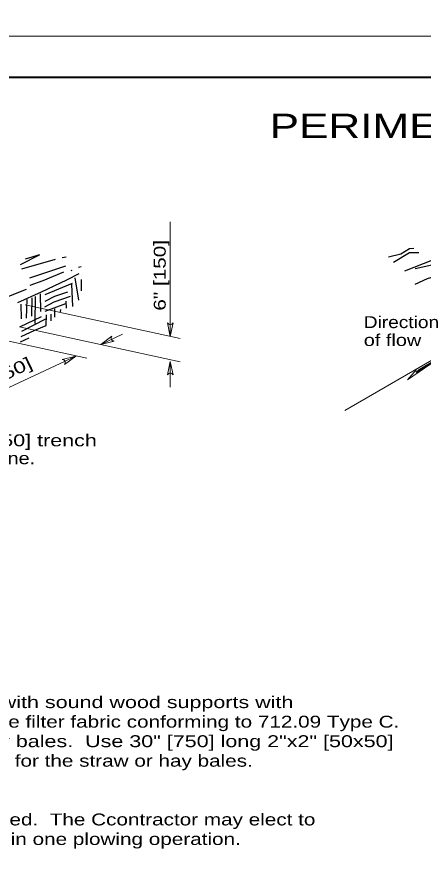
# Model space of a CAD drawing. Extents: x 1083.1 to 1117.1, y 672.5 to 716.5.
# Drawn here: x 1092.18 to 1097.5, y 683.63 to 694.76 of the extents above; entities that cross this region are included whole.
import ezdxf
from ezdxf.enums import TextEntityAlignment as Align

# ---------------------------------------------------------------- set-up
doc = ezdxf.new("R2010")
doc.units = 0
doc.header["$LTSCALE"] = 0.062
doc.linetypes.add('LONG_DASHED', pattern=[7.5, 6, -1.5])
doc.layers.add('1', color=7, linetype='Continuous', lineweight=13)

msp = doc.modelspace()

# ---------------------------------------------------------------- linework, layer by layer
at = {"layer": '1', "lineweight": 25}
for p, q in [((1085.14617, 693.96842), (1116.64617, 693.96842)), ((1092.24067, 691.4565), (1092.684, 691.58508)), ((1092.77267, 691.60783), (1092.82592, 691.61542)), ((1097.26167, 691.43017), (1097.63042, 691.5765)), ((1092.34708, 691.33925), (1092.81883, 691.49817)), ((1092.88975, 691.43758), (1092.90392, 691.44142)), ((1092.9855, 691.47925), (1093.021, 691.49058)), ((1097.61433, 691.50475), (1097.399, 691.45883)), ((1092.83358, 691.31283), (1092.99617, 691.396)), ((1092.98908, 691.048), (1092.94292, 691.33925)), ((1093.0245, 691.16908), (1093.0245, 691.31658)), ((1092.54925, 691.12367), (1092.9075, 691.27117)), ((1092.911, 690.96483), (1092.89683, 691.25608)), ((1092.29917, 691.18575), (1092.04742, 691.08583)), ((1092.418, 690.74167), (1092.4215, 691.09717)), ((1092.4925, 690.9005), (1092.48892, 691.13125)), ((1092.23708, 690.80217), (1092.23358, 690.99508)), ((1092.3045, 690.8135), (1092.31158, 691.05558)), ((1092.37183, 690.84), (1092.379, 691.07825)), ((1092.54925, 690.90433), (1092.81883, 691.00267)), ((1092.82942, 690.94208), (1092.82233, 691.03667)), ((1092.62725, 690.77567), (1092.62725, 690.86267)), ((1092.67692, 690.82483), (1092.67333, 690.93458)), ((1092.75142, 690.89675), (1092.75492, 690.927)), ((1092.21583, 690.70008), (1092.49958, 690.83242)), ((1092.24417, 690.6395), (1092.55633, 690.80217)), ((1092.22642, 690.49958), (1092.33992, 690.55258))]:
    msp.add_line(p, q, dxfattribs=at)
at = {"layer": '1'}
for p, q in [((1094.18892, 690.57275), (1094.18892, 692.07433)), ((1092.28458, 690.98833), (1094.31658, 690.54433)), ((1092.22783, 690.69583), (1094.31658, 690.2395)), ((1091.91592, 690.543), (1093.09275, 690.28583)), ((1093.27825, 690.46883), (1093.562, 690.60125)), ((1091.53567, 689.65442), (1092.9485, 690.3135)), ((1094.18892, 689.90975), (1094.18892, 690.24458))]:
    msp.add_line(p, q, dxfattribs=at)
at = {"layer": '1', "linetype": 'LONG_DASHED'}
for points in [[(1083.12642, 694.50825), (1117.12642, 694.50825), (1117.12642, 716.50825), (1083.12642, 716.50825)], [(1083.12642, 672.50825), (1117.12642, 672.50825), (1117.12642, 694.50825), (1083.12642, 694.50825)]]:
    msp.add_lwpolyline(points, close=True, dxfattribs=at)
at = {"layer": '1', "lineweight": 40}
msp.add_lwpolyline([(1085.14617, 693.96842), (1116.64617, 693.96842), (1116.64617, 672.96842), (1085.14617, 672.96842)], close=True, dxfattribs=at)
at = {"layer": '1', "lineweight": 25}
for points in [[(1092.22642, 691.517), (1092.47475, 691.64183), (1092.28675, 691.58508)], [(1097.04658, 691.6145), (1097.21, 691.65525), (1097.32233, 691.72467), (1097.381, 691.72708)], [(1097.11558, 691.54508), (1097.32483, 691.672), (1097.44742, 691.672)], [(1097.39625, 691.25792), (1097.55775, 691.33258), (1097.76233, 691.39283), (1097.94267, 691.456)], [(1092.19158, 691.01783), (1092.50017, 691.15775), (1092.83358, 691.31283)], [(1092.35058, 691.24467), (1092.52442, 691.30525), (1092.794, 691.41867)], [(1092.54217, 690.961), (1092.66625, 691.02533), (1092.87908, 691.101)], [(1092.54925, 691.03667), (1092.67692, 691.101), (1092.84358, 691.15775)], [(1092.23358, 690.57142), (1092.41442, 690.65467), (1092.56342, 690.71517), (1092.56692, 690.85517)]]:
    msp.add_lwpolyline(points, dxfattribs=at)
at = {"layer": '1'}
for points in [[(1094.22433, 690.74975), (1094.18892, 690.57275), (1094.1535, 690.74975), (1094.15367, 690.74975)], [(1093.45358, 690.51158), (1093.27825, 690.46883), (1093.42367, 690.57575), (1093.42375, 690.57567)], [(1096.47692, 689.6015), (1097.98042, 690.46958), (1097.29867, 690.00358), (1097.417, 690.14125)], [(1092.77308, 690.27075), (1092.9485, 690.3135), (1092.80308, 690.20658), (1092.803, 690.20675)], [(1094.1535, 690.06758), (1094.18892, 690.24458), (1094.22433, 690.06758), (1094.22425, 690.06758)], [(1097.41017, 690.09817), (1097.6515, 690.25558), (1097.44958, 690.139), (1097.41183, 690.10525)]]:
    msp.add_lwpolyline(points, dxfattribs=at)
for centre, start, end in [((1094.18903, 690.76414), 202.08789, 337.91402), ((1093.45172, 690.5497), 137.09778, 272.92391), ((1092.775, 690.23269), 317.09808, 92.92421), ((1094.18886, 690.05321), 22.08789, 157.91402)]:
    msp.add_arc(centre, 0.0382, start, end, dxfattribs=at)

# ---------------------------------------------------------------- texts
at = {"layer": '1', "width": 1.35}
msp.add_text('PERIMETER FILTER FABRIC FENCE', height=0.32, dxfattribs=at).set_placement((1100.44883, 693.17075), align=Align.CENTER)
at = {"layer": '1'}
for rotation, width, p in [(90, 1.3, (1094.12825, 690.91025)), (25.759, 1.4, (1091.495, 689.73658))]:
    msp.add_text('6" [150]', height=0.156, rotation=rotation, dxfattribs=dict(at, width=width)).set_placement(p)
for s, width, p in [('Direction', 1.2, (1096.72392, 690.68175)), ('of flow', 1.25, (1096.72392, 690.44708)), ('Excavate a 6"x6" [150x150] trench', 1.35, (1088.924, 689.13308)), ('along the proposed fence line.', 1.25, (1088.924, 688.89842)), ('             Furnish 30" [0.8 m] wide filter fabric with sound wood supports with', 1.35, (1086.46683, 685.70267)), ("maximum on-center spacing of 10' [3.0 m].  Use filter fabric conforming to 712.09 Type C.", 1.3, (1086.46683, 685.44667)), ('The Contractor may elect to use straw or hay bales.  Use 30" [750] long 2"x2" [50x50]', 1.35, (1086.46683, 685.19067)), ('wooden stakes, reinforcing bars or fence posts for the straw or hay bales.', 1.3, (1086.46683, 684.93467)), ('               Trench the filter fabric fence as detailed.  The Ccontractor may elect to', 1.3, (1086.50383, 684.16525)), ('trench the fence detailed on steps 1 through 3 in one plowing operation.', 1.3, (1086.50383, 683.90925))]:
    msp.add_text(s, height=0.156, dxfattribs=dict(at, width=width)).set_placement(p)

doc.saveas('drawing.dxf')
